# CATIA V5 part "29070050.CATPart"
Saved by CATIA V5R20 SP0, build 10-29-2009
Part number: 29070050
Definition: NONE
Nomenclature: 29070050
Source: Unknown
Description: 29070050
Bounding box of the stored display mesh (mm): x -25 to 44.548, y -49 to 83.548, z -39 to 39
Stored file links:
  C:\Users\Utente\Desktop\IO LAVORO\3D X SITO CF\X SITO\PLASTICA\RF1\29070050.CATPart
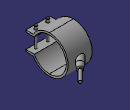
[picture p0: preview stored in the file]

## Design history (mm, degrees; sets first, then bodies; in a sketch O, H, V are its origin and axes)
Body1 "29070050" (main body)
  Solid1: solid without history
